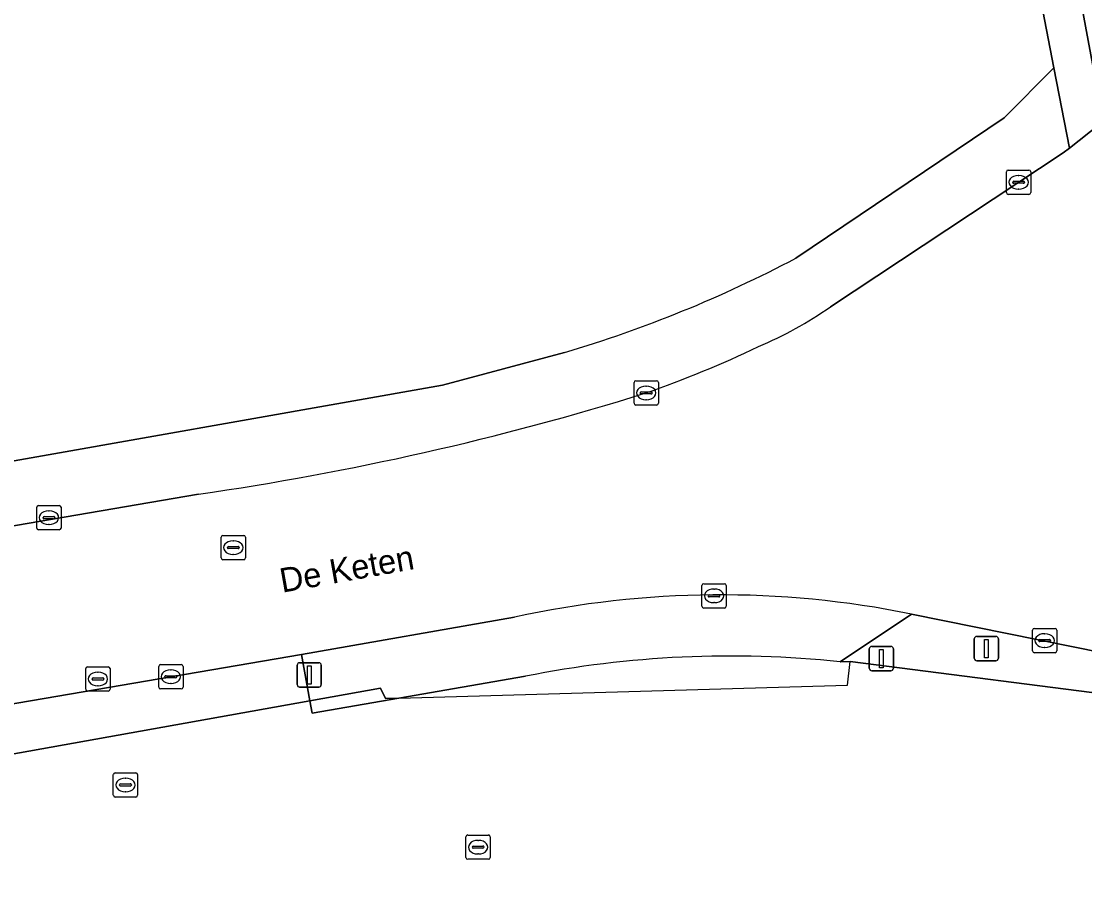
# Model space of a CAD drawing. Extents: x 156141 to 158132, y 385651 to 388333.
# Drawn here: x 156757.38 to 156801.13, y 386759.9 to 386795.58 of the extents above; entities that cross this region are included whole.
import ezdxf

# ---------------------------------------------------------------- set-up
doc = ezdxf.new("R2010")
doc.units = 0
for name, color, linetype in [('IMGEO_Berm_groen', 7, 'Continuous'), ('IMGEO_Erf', 7, 'Continuous'), ('IMGEO_Fietspad_open', 7, 'Continuous'), ('IMGEO_Groenvoorziening', 7, 'Continuous'), ('IMGEO_Hek', 7, 'Continuous'), ('IMGEO_Kolk', 7, 'Continuous'), ('IMGEO_Lichtmast', 7, 'Continuous'), ('IMGEO_Openbare_ruimte_label', 7, 'Continuous'), ('IMGEO_Rijbaan_lokaal_gesloten', 7, 'Continuous'), ('IMGEO_Rijbaan_lokaal_open', 7, 'Continuous'), ('IMGEO_Rioolput', 7, 'Continuous'), ('IMGEO_Verkeersbordpaal', 7, 'Continuous'), ('IMGEO_Voetpad_open', 7, 'Continuous')]:
    doc.layers.add(name, color=color, linetype=linetype)

msp = doc.modelspace()

# ---------------------------------------------------------------- linework, layer by layer
at = {"layer": 'IMGEO_Berm_groen'}
for points in [[(156790.673, 386783.83), (156800.246, 386790.17), (156800.502, 386790.354), (156799.862, 386793.67), (156797.816, 386791.602), (156789.25, 386785.838)], [(156779.733, 386781.96), (156774.709, 386780.609), (156754.356, 386777.018), (156753.838, 386777.245), (156753.33, 386777.099), (156756.662, 386774.763), (156764.664, 386776.13)], [(156769.252, 386767.626), (156768.912, 386769.526), (156752.445, 386766.717)], [(156746.642, 386765.322), (156746.853, 386762.833), (156751.247, 386764.398), (156769.252, 386767.626)]]:
    msp.add_lwpolyline(points, dxfattribs=at)
for centre, radius, start, end in [((156765.142, 386831.384), 51.532, 286.4474, 297.8926), ((156781.029, 386797.834), 17.003, 293.1166, 304.5524), ((156767.988, 386823.521), 45.787, 289.2449, 295.5067), ((156747.876, 386893.238), 118.306, 278.15806, 287.31166)]:
    msp.add_arc(centre, radius, start, end, dxfattribs=at)
at = {"layer": 'IMGEO_Erf'}
for points in [[(156789.25, 386785.838), (156797.816, 386791.602), (156799.862, 386793.67), (156786.023, 386865.361)], [(156735.926, 386771.688), (156738.237, 386772.522), (156738.301, 386772.773), (156738.577, 386772.853), (156753.33, 386777.099), (156753.838, 386777.245), (156754.356, 386777.018), (156774.709, 386780.609), (156779.733, 386781.96)], [(156811.397, 386735.567), (156811.153, 386735.5), (156807.14, 386749.598), (156803.451, 386767.705), (156791.477, 386769.248), (156791.068, 386769.236)], [(156778.117, 386768.64), (156772.911, 386767.737), (156769.343, 386767.119), (156769.252, 386767.626), (156751.247, 386764.398), (156746.853, 386762.833), (156744.759, 386762.087), (156742.455, 386761.134), (156742.214, 386761.034), (156741.07, 386760.537)]]:
    msp.add_lwpolyline(points, dxfattribs=at)
for centre, radius, start, end in [((156765.142, 386831.384), 51.532, 286.4474, 297.8926), ((156786.562, 386726.13), 43.34, 84.033, 101.2368)]:
    msp.add_arc(centre, radius, start, end, dxfattribs=at)
at = {"layer": 'IMGEO_Fietspad_open'}
msp.add_lwpolyline([(156802.289, 386802.533), (156802.367, 386802.045), (156800.014, 386801.586), (156801.853, 386791.693), (156801.763, 386791.359)], dxfattribs=at)
at = {"layer": 'IMGEO_Groenvoorziening'}
msp.add_lwpolyline([(156804.518, 386769.067), (156794.01, 386771.195), (156791.068, 386769.236), (156791.477, 386769.248), (156803.451, 386767.705), (156807.14, 386749.598), (156811.153, 386735.5), (156811.397, 386735.567)], dxfattribs=at)
at = {"layer": 'IMGEO_Hek'}
for points in [[(156799.862, 386793.67), (156797.816, 386791.602), (156789.25, 386785.838)], [(156753.33, 386777.099), (156753.838, 386777.245), (156754.356, 386777.018), (156774.709, 386780.609), (156779.733, 386781.96)], [(156772.911, 386767.737), (156791.371, 386768.275), (156791.477, 386769.248)], [(156791.477, 386769.248), (156803.451, 386767.705)], [(156769.252, 386767.626), (156772.15, 386768.146), (156772.358, 386767.721), (156772.911, 386767.737)], [(156742.214, 386761.034), (156742.055, 386761.609), (156751.247, 386764.398), (156769.252, 386767.626)]]:
    msp.add_lwpolyline(points, dxfattribs=at)
msp.add_arc((156765.142, 386831.384), 51.532, 286.4474, 297.8926, dxfattribs=at)
at = {"layer": 'IMGEO_Kolk'}
for p, q in [((156797.91, 386788.531), (156797.91, 386789.383)), ((156797.985, 386789.457), (156798.837, 386789.457)), ((156798.911, 386789.383), (156798.911, 386788.531)), ((156798.169, 386788.951), (156798.169, 386788.963)), ((156798.212, 386789), (156798.61, 386789)), ((156798.398, 386789.237), (156798.423, 386789.237)), ((156798.653, 386788.963), (156798.653, 386788.951)), ((156798.607, 386788.914), (156798.209, 386788.914)), ((156798.421, 386788.677), (156798.396, 386788.677)), ((156798.837, 386788.457), (156797.985, 386788.457)), ((156782.587, 386779.866), (156782.587, 386780.718)), ((156782.662, 386780.792), (156783.514, 386780.792)), ((156783.588, 386780.718), (156783.588, 386779.866)), ((156782.846, 386780.286), (156782.846, 386780.298)), ((156783.284, 386780.249), (156782.886, 386780.249)), ((156782.889, 386780.335), (156783.287, 386780.335)), ((156783.075, 386780.572), (156783.1, 386780.572)), ((156783.33, 386780.298), (156783.33, 386780.286)), ((156783.514, 386779.792), (156782.662, 386779.792)), ((156783.098, 386780.012), (156783.073, 386780.012)), ((156758.011, 386774.735), (156758.011, 386775.587)), ((156758.086, 386775.661), (156758.938, 386775.661)), ((156758.499, 386775.441), (156758.524, 386775.441)), ((156759.012, 386775.587), (156759.012, 386774.735)), ((156758.27, 386775.155), (156758.27, 386775.167)), ((156758.708, 386775.118), (156758.31, 386775.118)), ((156758.313, 386775.204), (156758.711, 386775.204)), ((156758.754, 386775.167), (156758.754, 386775.155)), ((156758.938, 386774.661), (156758.086, 386774.661)), ((156758.522, 386774.881), (156758.497, 386774.881)), ((156785.382, 386771.519), (156785.382, 386772.371)), ((156785.457, 386772.445), (156786.309, 386772.445)), ((156786.383, 386772.371), (156786.383, 386771.519)), ((156785.641, 386771.939), (156785.641, 386771.951)), ((156786.079, 386771.902), (156785.681, 386771.902)), ((156785.684, 386771.988), (156786.082, 386771.988)), ((156785.87, 386772.225), (156785.895, 386772.225)), ((156786.125, 386771.951), (156786.125, 386771.939)), ((156786.309, 386771.445), (156785.457, 386771.445)), ((156785.893, 386771.665), (156785.868, 386771.665)), ((156799.059, 386770.606), (156799.911, 386770.606)), ((156798.984, 386769.68), (156798.984, 386770.532)), ((156799.286, 386770.149), (156799.684, 386770.149)), ((156799.472, 386770.386), (156799.497, 386770.386)), ((156799.985, 386770.532), (156799.985, 386769.68)), ((156799.243, 386770.1), (156799.243, 386770.112)), ((156799.681, 386770.063), (156799.283, 386770.063)), ((156799.495, 386769.826), (156799.47, 386769.826)), ((156799.727, 386770.112), (156799.727, 386770.1)), ((156799.911, 386769.606), (156799.059, 386769.606)), ((156763.029, 386768.192), (156763.029, 386769.044)), ((156763.104, 386769.118), (156763.956, 386769.118)), ((156763.517, 386768.898), (156763.542, 386768.898)), ((156764.03, 386769.044), (156764.03, 386768.192)), ((156763.288, 386768.612), (156763.288, 386768.624)), ((156763.726, 386768.575), (156763.328, 386768.575)), ((156763.331, 386768.661), (156763.729, 386768.661)), ((156763.772, 386768.624), (156763.772, 386768.612)), ((156763.956, 386768.118), (156763.104, 386768.118)), ((156763.54, 386768.338), (156763.515, 386768.338))]:
    msp.add_line(p, q, dxfattribs=at)
for points in [[(156797.91, 386788.531), (156797.91, 386789.383)], [(156797.985, 386789.457), (156798.837, 386789.457)], [(156798.911, 386789.383), (156798.911, 386788.531)], [(156798.837, 386788.457), (156797.985, 386788.457)], [(156782.587, 386779.866), (156782.587, 386780.718)], [(156782.662, 386780.792), (156783.514, 386780.792)], [(156783.588, 386780.718), (156783.588, 386779.866)], [(156783.514, 386779.792), (156782.662, 386779.792)], [(156758.011, 386774.735), (156758.011, 386775.587)], [(156758.086, 386775.661), (156758.938, 386775.661)], [(156759.012, 386775.587), (156759.012, 386774.735)], [(156758.938, 386774.661), (156758.086, 386774.661)], [(156785.382, 386771.519), (156785.382, 386772.371)], [(156785.457, 386772.445), (156786.309, 386772.445)], [(156786.383, 386772.371), (156786.383, 386771.519)], [(156786.309, 386771.445), (156785.457, 386771.445)], [(156799.059, 386770.606), (156799.911, 386770.606)], [(156798.984, 386769.68), (156798.984, 386770.532)], [(156799.985, 386770.532), (156799.985, 386769.68)], [(156799.911, 386769.606), (156799.059, 386769.606)], [(156763.029, 386768.192), (156763.029, 386769.044)], [(156763.104, 386769.118), (156763.956, 386769.118)], [(156764.03, 386769.044), (156764.03, 386768.192)], [(156763.956, 386768.118), (156763.104, 386768.118)]]:
    msp.add_lwpolyline(points, dxfattribs=at)
for centre, radius, start, end in [((156797.987, 386789.381), 0.0765, 91.552, 178.448), ((156797.987, 386789.381), 0.0765, 91.552, 178.448), ((156798.835, 386789.381), 0.0765, 1.552, 88.448), ((156798.835, 386789.381), 0.0765, 1.552, 88.448), ((156798.209, 386788.96), 0.0403, 85.8775, 175.7526), ((156798.206, 386788.95), 0.0366, 178.938, 274.7102), ((156798.61, 386788.957), 0.043, 264.8664, 352.4533), ((156798.614, 386788.962), 0.0386, 1.7309, 96.639), ((156797.987, 386788.533), 0.0765, 181.552, 268.448), ((156797.987, 386788.533), 0.0765, 181.552, 268.448), ((156798.835, 386788.533), 0.0765, 271.552, 358.448), ((156798.835, 386788.533), 0.0765, 271.552, 358.448), ((156782.664, 386780.716), 0.0765, 91.552, 178.448), ((156782.664, 386780.716), 0.0765, 91.552, 178.448), ((156783.512, 386780.716), 0.0765, 1.552, 88.448), ((156783.512, 386780.716), 0.0765, 1.552, 88.448), ((156782.886, 386780.295), 0.0403, 85.8775, 175.7526), ((156782.883, 386780.285), 0.0366, 178.938, 274.7102), ((156783.287, 386780.292), 0.043, 264.8664, 352.4533), ((156783.291, 386780.297), 0.0386, 1.7309, 96.639), ((156782.664, 386779.868), 0.0765, 181.552, 268.448), ((156782.664, 386779.868), 0.0765, 181.552, 268.448), ((156783.512, 386779.868), 0.0765, 271.552, 358.448), ((156783.512, 386779.868), 0.0765, 271.552, 358.448), ((156758.088, 386775.585), 0.0765, 91.552, 178.448), ((156758.088, 386775.585), 0.0765, 91.552, 178.448), ((156758.936, 386775.585), 0.0765, 1.552, 88.448), ((156758.936, 386775.585), 0.0765, 1.552, 88.448), ((156758.31, 386775.164), 0.0403, 85.8775, 175.7526), ((156758.307, 386775.154), 0.0366, 178.938, 274.7102), ((156758.711, 386775.161), 0.043, 264.8664, 352.4533), ((156758.715, 386775.166), 0.0386, 1.7309, 96.639), ((156758.088, 386774.737), 0.0765, 181.552, 268.448), ((156758.088, 386774.737), 0.0765, 181.552, 268.448), ((156758.936, 386774.737), 0.0765, 271.552, 358.448), ((156758.936, 386774.737), 0.0765, 271.552, 358.448), ((156785.459, 386772.369), 0.0765, 91.552, 178.448), ((156785.459, 386772.369), 0.0765, 91.552, 178.448), ((156786.307, 386772.369), 0.0765, 1.552, 88.448), ((156786.307, 386772.369), 0.0765, 1.552, 88.448), ((156785.681, 386771.948), 0.0403, 85.8775, 175.7526), ((156785.678, 386771.938), 0.0366, 178.938, 274.7102), ((156786.082, 386771.945), 0.043, 264.8664, 352.4533), ((156786.086, 386771.95), 0.0386, 1.7309, 96.639), ((156785.459, 386771.521), 0.0765, 181.552, 268.448), ((156785.459, 386771.521), 0.0765, 181.552, 268.448), ((156786.307, 386771.521), 0.0765, 271.552, 358.448), ((156786.307, 386771.521), 0.0765, 271.552, 358.448), ((156799.061, 386770.53), 0.0765, 91.552, 178.448), ((156799.061, 386770.53), 0.0765, 91.552, 178.448), ((156799.909, 386770.53), 0.0765, 1.552, 88.448), ((156799.909, 386770.53), 0.0765, 1.552, 88.448), ((156799.283, 386770.109), 0.0403, 85.8775, 175.7526), ((156799.688, 386770.111), 0.0386, 1.7309, 96.639), ((156799.28, 386770.099), 0.0366, 178.938, 274.7102), ((156799.684, 386770.106), 0.043, 264.8664, 352.4533), ((156799.061, 386769.682), 0.0765, 181.552, 268.448), ((156799.061, 386769.682), 0.0765, 181.552, 268.448), ((156799.909, 386769.682), 0.0765, 271.552, 358.448), ((156799.909, 386769.682), 0.0765, 271.552, 358.448), ((156763.106, 386769.042), 0.0765, 91.552, 178.448), ((156763.106, 386769.042), 0.0765, 91.552, 178.448), ((156763.954, 386769.042), 0.0765, 1.552, 88.448), ((156763.954, 386769.042), 0.0765, 1.552, 88.448), ((156763.328, 386768.621), 0.0403, 85.8775, 175.7526), ((156763.325, 386768.611), 0.0366, 178.938, 274.7102), ((156763.729, 386768.618), 0.043, 264.8664, 352.4533), ((156763.733, 386768.623), 0.0386, 1.7309, 96.639), ((156763.106, 386768.194), 0.0765, 181.552, 268.448), ((156763.106, 386768.194), 0.0765, 181.552, 268.448), ((156763.954, 386768.194), 0.0765, 271.552, 358.448), ((156763.954, 386768.194), 0.0765, 271.552, 358.448)]:
    msp.add_arc(centre, radius, start, end, dxfattribs=at)
for centre, major_axis, ratio, start_param, end_param in [((156798.397, 386788.957), (-0.387, 0.002), 0.722429, 4.712389, 7.853982), ((156798.422, 386788.957), (-0.39, 0.002), 0.717154, 1.570796, 4.712389), ((156783.074, 386780.292), (-0.387, 0.002), 0.722429, 4.712389, 7.853982), ((156783.099, 386780.292), (-0.39, 0.002), 0.717154, 1.570796, 4.712389), ((156758.498, 386775.161), (-0.387, 0.002), 0.722429, 4.712389, 7.853982), ((156758.523, 386775.161), (-0.39, 0.002), 0.717154, 1.570796, 4.712389), ((156785.869, 386771.945), (-0.387, 0.002), 0.722429, 4.712389, 7.853982), ((156785.894, 386771.945), (-0.39, 0.002), 0.717154, 1.570796, 4.712389), ((156799.471, 386770.106), (-0.387, 0.002), 0.722429, 4.712389, 7.853982), ((156799.496, 386770.106), (-0.39, 0.002), 0.717154, 1.570796, 4.712389), ((156763.516, 386768.618), (-0.387, 0.002), 0.722429, 4.712389, 7.853982), ((156763.541, 386768.618), (-0.39, 0.002), 0.717154, 1.570796, 4.712389)]:
    msp.add_ellipse(centre, major_axis=major_axis, ratio=ratio, start_param=start_param, end_param=end_param, dxfattribs=at)
at = {"layer": 'IMGEO_Lichtmast'}
for p, q in [((156796.589, 386769.376), (156796.589, 386770.176)), ((156796.589, 386770.176), (156796.589, 386769.376)), ((156796.689, 386770.276), (156797.479, 386770.276)), ((156797.479, 386770.276), (156796.689, 386770.276)), ((156797.579, 386770.176), (156797.579, 386769.376)), ((156797.579, 386769.376), (156797.579, 386770.176)), ((156797.479, 386769.276), (156796.689, 386769.276)), ((156796.689, 386769.276), (156797.479, 386769.276)), ((156768.729, 386768.292), (156768.729, 386769.092)), ((156768.729, 386769.092), (156768.729, 386768.292)), ((156768.829, 386769.192), (156769.619, 386769.192)), ((156769.619, 386769.192), (156768.829, 386769.192)), ((156769.719, 386769.092), (156769.719, 386768.292)), ((156769.719, 386768.292), (156769.719, 386769.092)), ((156769.619, 386768.192), (156768.829, 386768.192)), ((156768.829, 386768.192), (156769.619, 386768.192))]:
    msp.add_line(p, q, dxfattribs=at)
for points in [[(156797.009, 386770.151), (156797.159, 386770.151), (156797.159, 386769.401), (156797.009, 386769.401), (156797.009, 386770.151)], [(156769.149, 386769.067), (156769.299, 386769.067), (156769.299, 386768.317), (156769.149, 386768.317), (156769.149, 386769.067)]]:
    msp.add_lwpolyline(points, dxfattribs=at)
for centre, start, end in [((156796.689, 386770.176), 90, 180), ((156796.689, 386770.176), 90, 180), ((156797.479, 386770.176), 0, 90), ((156797.479, 386770.176), 360, 90), ((156796.689, 386769.376), 180, 270), ((156796.689, 386769.376), 180, 270), ((156797.479, 386769.376), 270, 0), ((156797.479, 386769.376), 270, 0), ((156768.829, 386769.092), 90, 180), ((156768.829, 386769.092), 90, 180), ((156769.619, 386769.092), 0, 90), ((156769.619, 386769.092), 360, 90), ((156768.829, 386768.292), 180, 270), ((156768.829, 386768.292), 180, 270), ((156769.619, 386768.292), 270, 0), ((156769.619, 386768.292), 270, 0)]:
    msp.add_arc(centre, 0.1, start, end, dxfattribs=at)
at = {"layer": 'IMGEO_Rijbaan_lokaal_gesloten'}
for points in [[(156794.01, 386771.195), (156804.518, 386769.067), (156805.763, 386768.783), (156801.763, 386791.359), (156800.502, 386790.354), (156800.246, 386790.17), (156790.673, 386783.83)], [(156764.664, 386776.13), (156756.662, 386774.763)], [(156752.445, 386766.717), (156768.912, 386769.526), (156777.67, 386771.065)]]:
    msp.add_lwpolyline(points, dxfattribs=at)
for centre, radius, start, end in [((156781.029, 386797.834), 17.003, 293.1166, 304.5524), ((156767.988, 386823.521), 45.787, 289.2449, 295.5067), ((156747.876, 386893.238), 118.306, 278.15806, 287.31166), ((156786.147, 386732.523), 39.463, 78.5072, 102.4045)]:
    msp.add_arc(centre, radius, start, end, dxfattribs=at)
at = {"layer": 'IMGEO_Rijbaan_lokaal_open'}
for points in [[(156777.67, 386771.065), (156768.912, 386769.526), (156769.252, 386767.626), (156772.15, 386768.146), (156772.358, 386767.721), (156772.911, 386767.737), (156778.117, 386768.64)], [(156791.068, 386769.236), (156794.01, 386771.195)]]:
    msp.add_lwpolyline(points, dxfattribs=at)
msp.add_lwpolyline([(156769.343, 386767.119), (156772.911, 386767.737), (156772.358, 386767.721), (156772.15, 386768.146), (156769.252, 386767.626)], close=True, dxfattribs=at)
for centre, radius, start, end in [((156786.147, 386732.523), 39.463, 78.5072, 102.4045), ((156786.562, 386726.13), 43.34, 84.033, 101.2368)]:
    msp.add_arc(centre, radius, start, end, dxfattribs=at)
at = {"layer": 'IMGEO_Rioolput'}
for p, q in [((156765.599, 386773.503), (156765.599, 386774.355)), ((156765.674, 386774.429), (156766.526, 386774.429)), ((156766.087, 386774.209), (156766.112, 386774.209)), ((156766.6, 386774.355), (156766.6, 386773.503)), ((156765.858, 386773.923), (156765.858, 386773.935)), ((156766.296, 386773.886), (156765.898, 386773.886)), ((156765.901, 386773.972), (156766.299, 386773.972)), ((156766.11, 386773.649), (156766.085, 386773.649)), ((156766.342, 386773.935), (156766.342, 386773.923)), ((156766.526, 386773.429), (156765.674, 386773.429)), ((156760.027, 386768.1), (156760.027, 386768.952)), ((156760.102, 386769.026), (156760.954, 386769.026)), ((156761.028, 386768.952), (156761.028, 386768.1)), ((156760.286, 386768.52), (156760.286, 386768.532)), ((156760.724, 386768.483), (156760.326, 386768.483)), ((156760.329, 386768.569), (156760.727, 386768.569)), ((156760.515, 386768.806), (156760.54, 386768.806)), ((156760.77, 386768.532), (156760.77, 386768.52)), ((156760.954, 386768.026), (156760.102, 386768.026)), ((156760.538, 386768.246), (156760.513, 386768.246)), ((156761.163, 386763.74), (156761.163, 386764.592)), ((156761.238, 386764.666), (156762.09, 386764.666)), ((156761.651, 386764.446), (156761.676, 386764.446)), ((156762.164, 386764.592), (156762.164, 386763.74)), ((156761.422, 386764.16), (156761.422, 386764.172)), ((156761.86, 386764.123), (156761.462, 386764.123)), ((156761.465, 386764.209), (156761.863, 386764.209)), ((156761.906, 386764.172), (156761.906, 386764.16)), ((156762.09, 386763.666), (156761.238, 386763.666)), ((156761.674, 386763.886), (156761.649, 386763.886)), ((156775.673, 386761.182), (156775.673, 386762.034)), ((156775.748, 386762.108), (156776.6, 386762.108)), ((156776.161, 386761.888), (156776.186, 386761.888)), ((156776.674, 386762.034), (156776.674, 386761.182)), ((156775.932, 386761.602), (156775.932, 386761.614)), ((156776.37, 386761.565), (156775.972, 386761.565)), ((156775.975, 386761.651), (156776.373, 386761.651)), ((156776.416, 386761.614), (156776.416, 386761.602)), ((156776.6, 386761.108), (156775.748, 386761.108)), ((156776.184, 386761.328), (156776.159, 386761.328))]:
    msp.add_line(p, q, dxfattribs=at)
for points in [[(156765.599, 386773.503), (156765.599, 386774.355)], [(156765.674, 386774.429), (156766.526, 386774.429)], [(156766.6, 386774.355), (156766.6, 386773.503)], [(156766.526, 386773.429), (156765.674, 386773.429)], [(156760.027, 386768.1), (156760.027, 386768.952)], [(156760.102, 386769.026), (156760.954, 386769.026)], [(156761.028, 386768.952), (156761.028, 386768.1)], [(156760.954, 386768.026), (156760.102, 386768.026)], [(156761.163, 386763.74), (156761.163, 386764.592)], [(156761.238, 386764.666), (156762.09, 386764.666)], [(156762.164, 386764.592), (156762.164, 386763.74)], [(156762.09, 386763.666), (156761.238, 386763.666)], [(156775.673, 386761.182), (156775.673, 386762.034)], [(156775.748, 386762.108), (156776.6, 386762.108)], [(156776.674, 386762.034), (156776.674, 386761.182)], [(156776.6, 386761.108), (156775.748, 386761.108)]]:
    msp.add_lwpolyline(points, dxfattribs=at)
for centre, radius, start, end in [((156765.676, 386774.353), 0.0765, 91.552, 178.448), ((156765.676, 386774.353), 0.0765, 91.552, 178.448), ((156766.524, 386774.353), 0.0765, 1.552, 88.448), ((156766.524, 386774.353), 0.0765, 1.552, 88.448), ((156765.898, 386773.932), 0.0403, 85.8775, 175.7526), ((156765.895, 386773.922), 0.0366, 178.938, 274.7102), ((156766.299, 386773.929), 0.043, 264.8664, 352.4533), ((156766.303, 386773.934), 0.0386, 1.7309, 96.639), ((156765.676, 386773.505), 0.0765, 181.552, 268.448), ((156765.676, 386773.505), 0.0765, 181.552, 268.448), ((156766.524, 386773.505), 0.0765, 271.552, 358.448), ((156766.524, 386773.505), 0.0765, 271.552, 358.448), ((156760.104, 386768.95), 0.0765, 91.552, 178.448), ((156760.104, 386768.95), 0.0765, 91.552, 178.448), ((156760.952, 386768.95), 0.0765, 1.552, 88.448), ((156760.952, 386768.95), 0.0765, 1.552, 88.448), ((156760.326, 386768.529), 0.0403, 85.8775, 175.7526), ((156760.323, 386768.519), 0.0366, 178.938, 274.7102), ((156760.727, 386768.526), 0.043, 264.8664, 352.4533), ((156760.731, 386768.531), 0.0386, 1.7309, 96.639), ((156760.104, 386768.102), 0.0765, 181.552, 268.448), ((156760.104, 386768.102), 0.0765, 181.552, 268.448), ((156760.952, 386768.102), 0.0765, 271.552, 358.448), ((156760.952, 386768.102), 0.0765, 271.552, 358.448), ((156761.24, 386764.59), 0.0765, 91.552, 178.448), ((156761.24, 386764.59), 0.0765, 91.552, 178.448), ((156762.088, 386764.59), 0.0765, 1.552, 88.448), ((156762.088, 386764.59), 0.0765, 1.552, 88.448), ((156761.462, 386764.169), 0.0403, 85.8775, 175.7526), ((156761.459, 386764.159), 0.0366, 178.938, 274.7102), ((156761.863, 386764.166), 0.043, 264.8664, 352.4533), ((156761.867, 386764.171), 0.0386, 1.7309, 96.639), ((156761.24, 386763.742), 0.0765, 181.552, 268.448), ((156761.24, 386763.742), 0.0765, 181.552, 268.448), ((156762.088, 386763.742), 0.0765, 271.552, 358.448), ((156762.088, 386763.742), 0.0765, 271.552, 358.448), ((156775.75, 386762.032), 0.0765, 91.552, 178.448), ((156775.75, 386762.032), 0.0765, 91.552, 178.448), ((156776.598, 386762.032), 0.0765, 1.552, 88.448), ((156776.598, 386762.032), 0.0765, 1.552, 88.448), ((156775.972, 386761.611), 0.0403, 85.8775, 175.7526), ((156775.969, 386761.601), 0.0366, 178.938, 274.7102), ((156776.373, 386761.608), 0.043, 264.8664, 352.4533), ((156776.377, 386761.613), 0.0386, 1.7309, 96.639), ((156775.75, 386761.184), 0.0765, 181.552, 268.448), ((156775.75, 386761.184), 0.0765, 181.552, 268.448), ((156776.598, 386761.184), 0.0765, 271.552, 358.448), ((156776.598, 386761.184), 0.0765, 271.552, 358.448)]:
    msp.add_arc(centre, radius, start, end, dxfattribs=at)
for centre, major_axis, ratio, start_param, end_param in [((156766.086, 386773.929), (-0.387, 0.002), 0.722429, 4.712389, 7.853982), ((156766.111, 386773.929), (-0.39, 0.002), 0.717154, 1.570796, 4.712389), ((156760.514, 386768.526), (-0.387, 0.002), 0.722429, 4.712389, 7.853982), ((156760.539, 386768.526), (-0.39, 0.002), 0.717154, 1.570796, 4.712389), ((156761.65, 386764.166), (-0.387, 0.002), 0.722429, 4.712389, 7.853982), ((156761.675, 386764.166), (-0.39, 0.002), 0.717154, 1.570796, 4.712389), ((156776.16, 386761.608), (-0.387, 0.002), 0.722429, 4.712389, 7.853982), ((156776.185, 386761.608), (-0.39, 0.002), 0.717154, 1.570796, 4.712389)]:
    msp.add_ellipse(centre, major_axis=major_axis, ratio=ratio, start_param=start_param, end_param=end_param, dxfattribs=at)
at = {"layer": 'IMGEO_Verkeersbordpaal'}
for p, q in [((156792.268, 386768.965), (156792.268, 386769.765)), ((156792.268, 386769.765), (156792.268, 386768.965)), ((156792.368, 386769.865), (156793.158, 386769.865)), ((156793.158, 386769.865), (156792.368, 386769.865)), ((156793.258, 386769.765), (156793.258, 386768.965)), ((156793.258, 386768.965), (156793.258, 386769.765)), ((156793.158, 386768.865), (156792.368, 386768.865)), ((156792.368, 386768.865), (156793.158, 386768.865))]:
    msp.add_line(p, q, dxfattribs=at)
msp.add_lwpolyline([(156792.688, 386769.74), (156792.838, 386769.74), (156792.838, 386768.99), (156792.688, 386768.99), (156792.688, 386769.74)], dxfattribs=at)
for centre, start, end in [((156792.368, 386769.765), 90, 180), ((156792.368, 386769.765), 90, 180), ((156793.158, 386769.765), 0, 90), ((156793.158, 386769.765), 360, 90), ((156792.368, 386768.965), 180, 270), ((156792.368, 386768.965), 180, 270), ((156793.158, 386768.965), 270, 0), ((156793.158, 386768.965), 270, 0)]:
    msp.add_arc(centre, 0.1, start, end, dxfattribs=at)
at = {"layer": 'IMGEO_Voetpad_open'}
msp.add_lwpolyline([(156786.023, 386865.361), (156799.862, 386793.67), (156800.502, 386790.354), (156801.763, 386791.359), (156801.853, 386791.693), (156800.014, 386801.586), (156787.566, 386865.893)], dxfattribs=at)

# ---------------------------------------------------------------- texts
at = {"layer": 'IMGEO_Openbare_ruimte_label'}
msp.add_text('De Keten', height=1, rotation=10.1408, dxfattribs=at).set_placement((156768.11, 386772.071))

doc.saveas('drawing.dxf')
